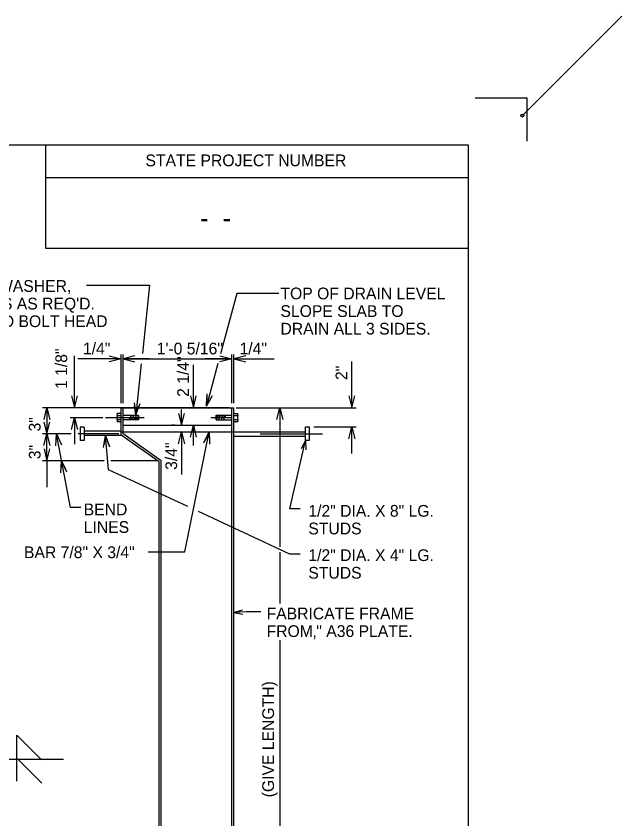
# Model space of a CAD drawing. Extents: x 973.2 to 1069.7, y 1484.4 to 1549.5.
# Drawn here: x 1052.53 to 1069.72, y 1525.25 to 1548.03 of the extents above; entities that cross this region are included whole.
import ezdxf

# ---------------------------------------------------------------- set-up
doc = ezdxf.new("R2010")
doc.units = 0
for name, color, linetype in [('Level 1', 7, 'Continuous'), ('Level 2', 7, 'Continuous'), ('Level 49', 7, 'Continuous')]:
    doc.layers.add(name, color=color, linetype=linetype)

msp = doc.modelspace()

# ---------------------------------------------------------------- linework, layer by layer
at = {"layer": 'Level 1'}
for p, q in [((1067.033, 1545.696), (1065.557, 1545.696)), ((1067.033, 1544.484), (1067.033, 1545.696)), ((1065.368, 1544.364), (981.8, 1544.364)), ((1053.366, 1544.364), (1053.366, 1541.447)), ((1065.368, 1488.431), (1065.368, 1544.364)), ((1053.366, 1543.446), (1065.368, 1543.446)), ((1053.366, 1541.447), (1065.368, 1541.447))]:
    msp.add_line(p, q, dxfattribs=at)
at = {"layer": 'Level 2'}
for p, q in [((1066.897, 1545.205), (1069.722, 1548.03)), ((1054.529, 1540.395), (1056.319, 1540.395)), ((1056.319, 1540.395), (1056.116, 1538.454)), ((1058.792, 1540.156), (1058.334, 1538.444)), ((1059.99, 1540.156), (1058.792, 1540.156)), ((1054.19, 1536.917), (1054.19, 1538.385)), ((1055.51, 1538.304), (1054.285, 1538.304)), ((1055.51, 1537.042), (1055.51, 1538.429)), ((1055.572, 1537.042), (1055.572, 1538.429)), ((1055.572, 1538.304), (1058.651, 1538.304)), ((1056.322, 1538.304), (1055.572, 1538.304)), ((1058.651, 1538.304), (1057.901, 1538.304)), ((1058.651, 1537.042), (1058.651, 1538.429)), ((1058.713, 1537.042), (1058.713, 1538.429)), ((1058.713, 1538.304), (1059.854, 1538.304)), ((1062.055, 1536.917), (1062.055, 1538.23)), ((1056.086, 1538.165), (1055.934, 1536.716)), ((1057.563, 1536.917), (1057.563, 1538.135)), ((1058.261, 1538.17), (1057.938, 1536.964)), ((1057.938, 1536.964), (1057.943, 1537.232)), ((1057.938, 1536.964), (1058.068, 1537.199)), ((1055.385, 1536.917), (1053.283, 1536.917)), ((1058.588, 1536.917), (1053.283, 1536.917)), ((1053.408, 1536.917), (1053.408, 1536.174)), ((1054.19, 1536.917), (1054.19, 1536.917)), ((1055.51, 1536.917), (1058.713, 1536.917)), ((1055.51, 1536.142), (1055.51, 1536.917)), ((1055.572, 1536.174), (1055.572, 1536.917)), ((1055.934, 1536.716), (1055.897, 1536.982)), ((1055.934, 1536.716), (1056.026, 1536.968)), ((1057.091, 1536.917), (1057.206, 1536.917)), ((1057.227, 1536.417), (1057.227, 1536.869)), ((1058.651, 1523.167), (1058.651, 1536.917)), ((1058.713, 1523.17), (1058.713, 1536.917)), ((1058.776, 1536.917), (1062.18, 1536.917)), ((1058.838, 1536.917), (1060.142, 1536.917)), ((1060.017, 1536.917), (1060.017, 1532.968)), ((1054.998, 1536.633), (1054.065, 1536.633)), ((1054.19, 1536.633), (1054.19, 1535.883)), ((1056.162, 1536.633), (1055.074, 1536.633)), ((1055.403, 1536.686), (1055.396, 1536.697)), ((1055.398, 1536.74), (1055.401, 1536.75)), ((1055.398, 1536.74), (1055.398, 1536.529)), ((1055.509, 1536.686), (1055.398, 1536.686)), ((1055.398, 1536.675), (1055.403, 1536.686)), ((1055.509, 1536.75), (1055.401, 1536.75)), ((1056.01, 1536.695), (1055.573, 1536.695)), ((1055.753, 1536.652), (1055.747, 1536.598)), ((1055.782, 1536.684), (1055.771, 1536.58)), ((1055.821, 1536.654), (1055.816, 1536.6)), ((1055.85, 1536.686), (1055.839, 1536.582)), ((1055.898, 1536.654), (1055.893, 1536.6)), ((1055.927, 1536.686), (1055.916, 1536.582)), ((1055.967, 1536.656), (1055.961, 1536.602)), ((1055.996, 1536.688), (1055.985, 1536.584)), ((1056.01, 1536.695), (1056.01, 1536.57)), ((1058.06, 1536.638), (1058.65, 1536.638)), ((1058.212, 1536.576), (1058.212, 1536.701)), ((1058.212, 1536.701), (1058.65, 1536.701)), ((1058.227, 1536.583), (1058.238, 1536.687)), ((1058.256, 1536.615), (1058.262, 1536.669)), ((1058.296, 1536.586), (1058.306, 1536.69)), ((1058.325, 1536.618), (1058.33, 1536.671)), ((1058.373, 1536.585), (1058.383, 1536.689)), ((1058.402, 1536.617), (1058.407, 1536.671)), ((1058.441, 1536.588), (1058.452, 1536.692)), ((1058.47, 1536.62), (1058.476, 1536.673)), ((1058.714, 1536.756), (1058.82, 1536.756)), ((1058.714, 1536.694), (1058.825, 1536.694)), ((1058.826, 1536.709), (1058.819, 1536.695)), ((1058.819, 1536.695), (1058.824, 1536.681)), ((1058.825, 1536.742), (1058.82, 1536.756)), ((1058.826, 1536.707), (1058.822, 1536.692)), ((1058.822, 1536.692), (1058.824, 1536.68)), ((1058.826, 1536.71), (1058.824, 1536.696)), ((1058.824, 1536.696), (1058.826, 1536.684)), ((1058.825, 1536.531), (1058.825, 1536.742)), ((1055.399, 1536.575), (1055.397, 1536.587)), ((1055.397, 1536.564), (1055.401, 1536.579)), ((1055.397, 1536.562), (1055.403, 1536.577)), ((1055.397, 1536.562), (1055.399, 1536.575)), ((1055.401, 1536.579), (1055.398, 1536.592)), ((1055.403, 1536.577), (1055.398, 1536.59)), ((1055.509, 1536.577), (1055.398, 1536.577)), ((1055.398, 1536.529), (1055.403, 1536.516)), ((1055.509, 1536.516), (1055.403, 1536.516)), ((1055.572, 1536.417), (1058.651, 1536.417)), ((1056.01, 1536.57), (1055.573, 1536.57)), ((1057.025, 1536.417), (1056.956, 1536.417)), ((1057.563, 1535.842), (1057.563, 1536.417)), ((1058.212, 1536.576), (1058.65, 1536.576)), ((1058.714, 1536.585), (1058.825, 1536.585)), ((1058.714, 1536.521), (1058.822, 1536.521)), ((1058.824, 1536.596), (1058.82, 1536.585)), ((1058.82, 1536.585), (1058.827, 1536.574)), ((1058.825, 1536.531), (1058.822, 1536.521)), ((1054.1, 1536.174), (1053.283, 1536.174)), ((1053.408, 1535.424), (1053.408, 1536.174)), ((1054.072, 1534.087), (1053.68, 1536.174)), ((1055.447, 1536.174), (1054.297, 1536.174)), ((1054.352, 1536.366), (1054.352, 1535.99)), ((1054.466, 1536.366), (1054.352, 1536.366)), ((1054.466, 1536.366), (1054.466, 1535.99)), ((1055.494, 1536.252), (1054.494, 1536.252)), ((1055.51, 1536.23), (1058.713, 1536.23)), ((1055.572, 1536.229), (1058.651, 1536.229)), ((1056.651, 1535.414), (1055.572, 1536.174)), ((1057.16, 1536.229), (1057.206, 1536.229)), ((1057.227, 1536.229), (1057.227, 1535.025)), ((1057.317, 1532.823), (1058.009, 1536.229)), ((1058.009, 1536.23), (1057.894, 1535.988)), ((1058.009, 1536.23), (1058.021, 1535.962)), ((1058.716, 1536.234), (1060.716, 1536.234)), ((1059.462, 1536.173), (1061.222, 1536.173)), ((1060.744, 1535.995), (1060.744, 1536.371)), ((1060.744, 1536.371), (1060.858, 1536.371)), ((1060.858, 1535.995), (1060.858, 1536.371)), ((1060.983, 1536.371), (1062.18, 1536.371)), ((1062.055, 1535.621), (1062.055, 1536.371)), ((1054.466, 1535.99), (1054.352, 1535.99)), ((1055.494, 1536.127), (1054.494, 1536.127)), ((1055.068, 1536.127), (1055.026, 1535.862)), ((1055.068, 1536.127), (1055.155, 1535.873)), ((1055.156, 1535.157), (1055.068, 1536.127)), ((1056.588, 1535.381), (1055.51, 1536.142)), ((1058.716, 1536.109), (1060.716, 1536.109)), ((1060.304, 1534.044), (1060.744, 1535.991)), ((1060.744, 1535.991), (1060.623, 1535.752)), ((1060.744, 1535.995), (1060.858, 1535.995)), ((1060.744, 1535.991), (1060.75, 1535.723)), ((1055.035, 1535.414), (1053.283, 1535.414)), ((1053.408, 1535.414), (1053.408, 1534.664)), ((1053.823, 1535.414), (1053.807, 1535.146)), ((1053.823, 1535.414), (1053.935, 1535.17)), ((1056.526, 1535.414), (1055.224, 1535.414)), ((1056.588, 1523.17), (1056.588, 1535.381)), ((1056.651, 1523.167), (1056.651, 1535.414)), ((1057.405, 1534.111), (1055.156, 1535.157)), ((1054.366, 1534.087), (1054.072, 1534.087)), ((1060.304, 1532.763), (1057.712, 1533.969)), ((1060.591, 1534.044), (1060.304, 1534.044)), ((1056.278, 1532.823), (1057.317, 1532.823)), ((1060.017, 1532.817), (1060.017, 1531.364)), ((1060.591, 1532.763), (1060.304, 1532.763)), ((1058.702, 1531.105), (1058.958, 1531.184)), ((1059.064, 1531.124), (1058.702, 1531.105)), ((1058.702, 1531.105), (1058.965, 1531.054)), ((1059.478, 1531.124), (1059.064, 1531.124)), ((1060.017, 1530.323), (1060.017, 1523.167)), ((1052.556, 1527.626), (1053.252, 1526.93)), ((1052.556, 1526.324), (1052.556, 1527.626)), ((1052.556, 1527.626), (1053.252, 1526.93)), ((1051.451, 1526.946), (1053.881, 1526.946)), ((1052.572, 1526.955), (1053.268, 1526.259))]:
    msp.add_line(p, q, dxfattribs=at)
for points in [[(1055.177, 1538.387), (1055.51, 1538.304), (1055.177, 1538.221)], [(1055.906, 1538.387), (1055.572, 1538.304), (1055.906, 1538.221)], [(1058.317, 1538.387), (1058.651, 1538.304), (1058.317, 1538.221)], [(1059.047, 1538.387), (1058.713, 1538.304), (1059.047, 1538.221)], [(1057.944, 1537.308), (1057.938, 1536.964), (1058.105, 1537.265)], [(1054.107, 1537.25), (1054.19, 1536.917), (1054.273, 1537.25)], [(1057.48, 1537.25), (1057.563, 1536.917), (1057.646, 1537.25)], [(1061.972, 1537.25), (1062.055, 1536.917), (1062.139, 1537.25)], [(1053.325, 1536.583), (1053.408, 1536.917), (1053.492, 1536.583)], [(1055.886, 1537.057), (1055.934, 1536.716), (1056.052, 1537.039)], [(1059.934, 1536.583), (1060.017, 1536.917), (1060.101, 1536.583)], [(1054.107, 1536.299), (1054.19, 1536.633), (1054.273, 1536.299)], [(1057.144, 1536.75), (1057.227, 1536.417), (1057.311, 1536.75)], [(1053.324, 1536.507), (1053.408, 1536.174), (1053.491, 1536.507)], [(1057.48, 1536.083), (1057.563, 1536.417), (1057.646, 1536.083)], [(1053.324, 1535.84), (1053.408, 1536.174), (1053.491, 1535.84)], [(1053.66, 1535.831), (1053.68, 1536.174), (1053.824, 1535.862)], [(1057.144, 1535.896), (1057.227, 1536.229), (1057.311, 1535.896)], [(1057.861, 1535.919), (1058.009, 1536.23), (1058.024, 1535.886)], [(1061.972, 1536.038), (1062.055, 1536.371), (1062.139, 1536.038)], [(1055.014, 1535.787), (1055.068, 1536.127), (1055.18, 1535.802)], [(1053.325, 1535.747), (1053.408, 1535.414), (1053.492, 1535.747)], [(1053.802, 1535.071), (1053.823, 1535.414), (1053.966, 1535.101)]]:
    msp.add_lwpolyline(points, dxfattribs=at)
at = {"layer": 'Level 49'}
msp.add_circle((1066.896, 1545.205), 0.0404, dxfattribs=at)

# ---------------------------------------------------------------- texts
at = {"layer": 'Level 1'}
for s, height, p in [('STATE PROJECT NUMBER', 0.3336, (1056.203, 1543.768)), ('    -  -  ', 0.5387, (1056.953, 1542.029))]:
    msp.add_text(s, height=height, dxfattribs=at).set_placement(p)
at = {"layer": 'Level 2'}
for s, height, p in [('1/2" DIA.  BOLT,  LOCKWASHER,  ', 0.33333, (1047.253, 1540.204)), ('TOP OF DRAIN LEVEL', 0.33333, (1060.033, 1539.992)), ("NUT, & SLOTTED SHIMS AS REQ'D.", 0.33333, (1047.253, 1539.704)), ('SLOPE SLAB TO ', 0.33333, (1060.033, 1539.492)), ('FOR TIGHTENING WELD BOLT HEAD ', 0.33333, (1047.253, 1539.204)), ('DRAIN ALL 3 SIDES.', 0.33333, (1060.033, 1538.992)), (' 1/4"', 0.3333, (1054.306, 1538.429)), ('1\'-0 5/16"', 0.3333, (1056.522, 1538.429)), (' 1/4"', 0.3333, (1058.749, 1538.429)), ('BEND ', 0.3333, (1054.452, 1533.864)), ('1/2" DIA. X 8" LG.', 0.33333, (1060.825, 1533.823)), ('LINES', 0.3333, (1054.452, 1533.364)), ('STUDS ', 0.3333, (1060.825, 1533.323)), ('BAR 7/8" X 3/4"', 0.33333, (1052.757, 1532.648)), ('1/2" DIA. X 4" LG.', 0.33333, (1060.825, 1532.566)), ('STUDS ', 0.3333, (1060.825, 1532.066)), ('FABRICATE FRAME ', 0.33333, (1059.64, 1530.911)), ('FROM‚" A36 PLATE.', 0.33333, (1059.64, 1530.411))]:
    msp.add_text(s, height=height, dxfattribs=at).set_placement(p)
for s, height, p in [('1 1/8"', 0.3333, (1053.982, 1537.448)), ('2 1/4"', 0.3333, (1057.438, 1537.224)), ('2"', 0.3333, (1061.93, 1537.702)), (' 3"', 0.3333, (1053.228, 1536.119)), (' 3"', 0.3333, (1053.228, 1535.331)), (' 3/4"', 0.3333, (1057.102, 1535.029)), ('(GIVE LENGTH)', 0.33333, (1059.851, 1525.862))]:
    msp.add_text(s, height=height, rotation=90, dxfattribs=at).set_placement(p)

doc.saveas('drawing.dxf')
